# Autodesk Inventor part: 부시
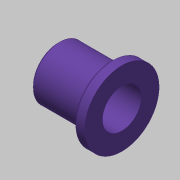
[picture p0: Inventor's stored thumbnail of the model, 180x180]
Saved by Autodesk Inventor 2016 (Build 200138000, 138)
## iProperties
Created: 2019-10
Part Number: 부시
Material: 강철, 연강
Document SubType Name: Modeling
Designer: mduedu
Density: 1 g/cm^3
Appearance: 보라색
Author: mduedu
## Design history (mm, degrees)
sketch "스케치1"
  geometry: L1 (0, 0)-(-18, 0); L2 (0, -5.5)-(0, -10.5); L3 (0, -10.5)-(-3, -10.5); L4 (-3, -10.5)-(-3, -7.5); L5 (-3, -7.5)-(-18, -7.5); L6 (-18, -7.5)-(-18, -5.5); L7 (-18, -5.5)-(0, -5.5)
  constraints: 14 end point, 3 parallel, 2 horizontal, 2 perpendicular, 2 vertical alignment
  dimensions: "d0" = 18 distance of L1.start L1.end; "d1" = 11 diameter of L7 L1; "d2" = 15 diameter of L5 L1; "d3" = 21 diameter of L3 L1; "d4" = 3 distance of L2.end L3.end
revolve "회전1" sketch "스케치1" stored, may be unused: angle "d5" = 90 deg
chamfer "모따기1" distance "d6" = 0.5; stored, may be unused: second distance "d7" = 2, angle "d8" = 45 deg
chamfer "모따기2" distance "d9" = 0.5; stored, may be unused: second distance "d10" = 2, angle "d11" = 45 deg
node "솔리드1"
